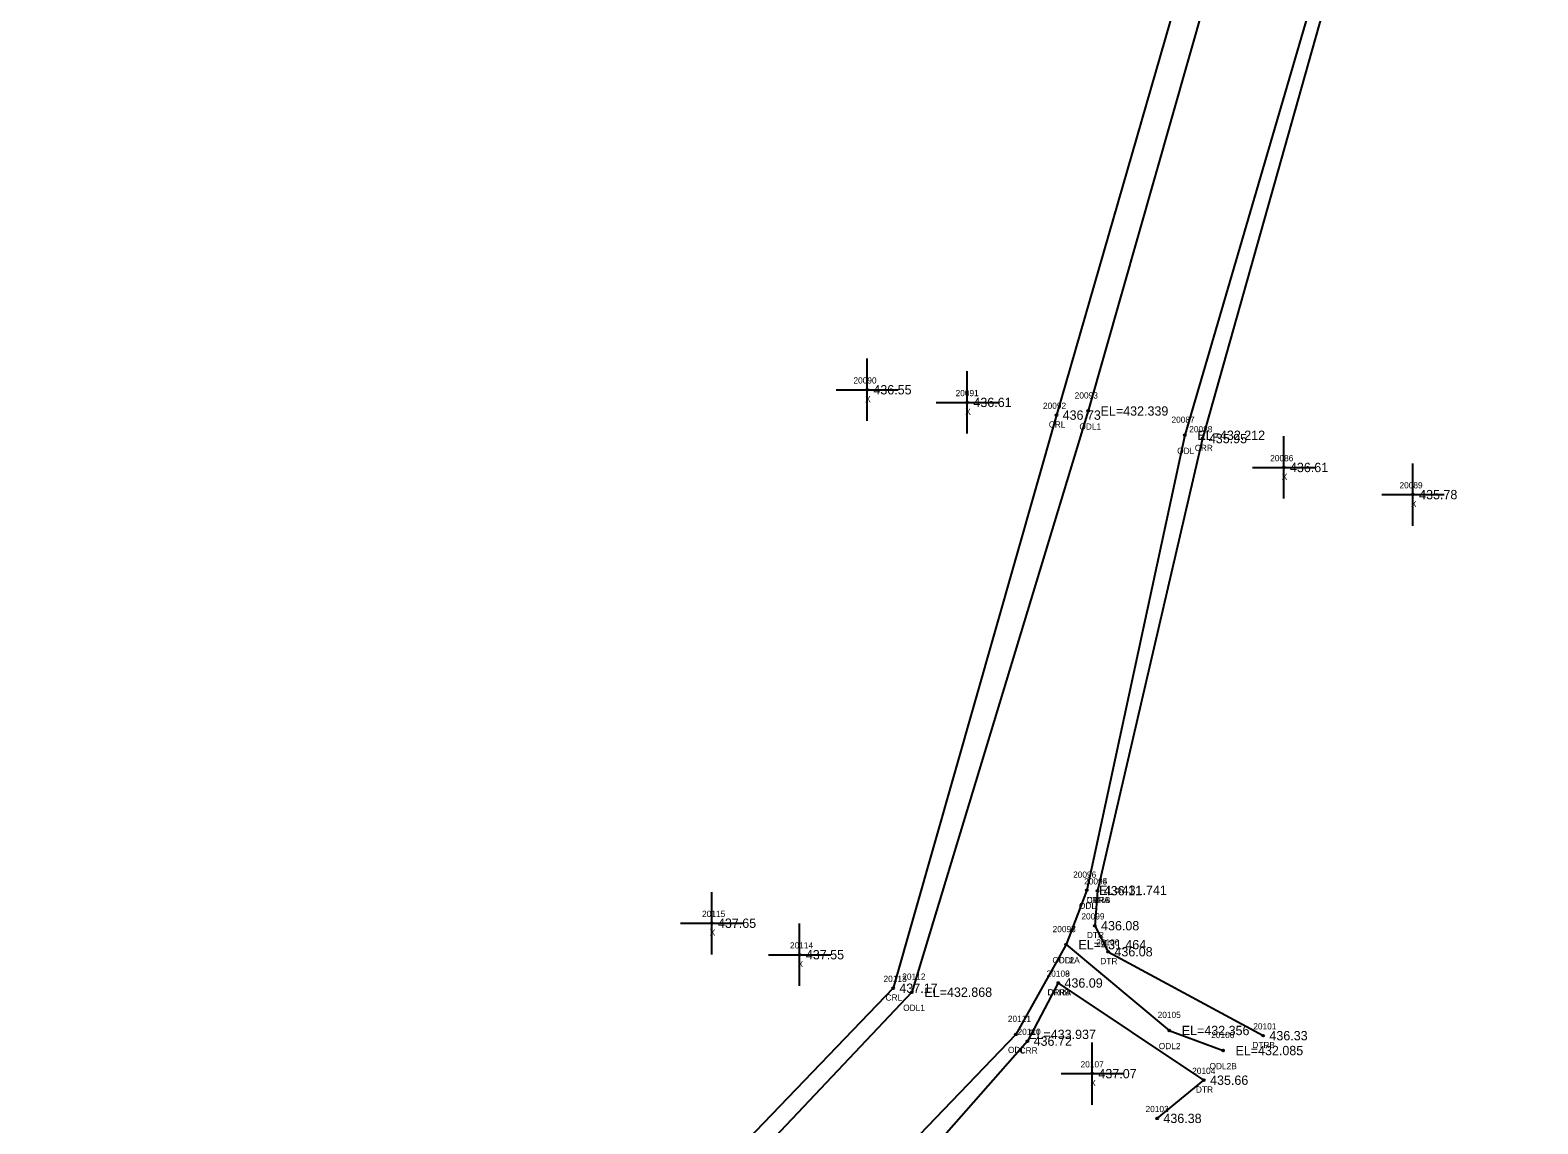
# Model space of a CAD drawing. Extents: x 1810114 to 1811498, y 790790 to 791824.
# Drawn here: x 1810544.9 to 1810787, y 790960.3 to 791135.9 of the extents above; entities that cross this region are included whole.
import ezdxf

# ---------------------------------------------------------------- set-up
doc = ezdxf.new("R2010")
doc.units = 0
for name, color, linetype in [('RD_EX_H2O', 7, 'Continuous'), ('RD_EX_H2O_txCode', 7, 'Continuous'), ('RD_EX_Misc', 7, 'Continuous'), ('RD_EX_Misc_txCode', 7, 'Continuous'), ('RD_EX_TX_H2O_ELEV', 7, 'Continuous'), ('RD_EX_TX_Misc_ELEV', 7, 'Continuous'), ('RD_SMD_Locator', 7, 'Continuous')]:
    doc.layers.add(name, color=color, linetype=linetype)

msp = doc.modelspace()

# ---------------------------------------------------------------- linework, layer by layer
at = {"layer": 'RD_EX_H2O'}
for points in [[(1810767.47, 791275.24), (1810763.99, 791268.4), (1810740.03, 791179.13), (1810709.69, 791074.11), (1810683.47, 790982.07), (1810621.06, 790917.07), (1810544.86, 790829.8)], [(1810771.9, 791274.91), (1810769.68, 791267.55), (1810744.28, 791178.39), (1810714.79, 791074.77), (1810686.49, 790981.43), (1810623.11, 790914.39), (1810548.58, 790826.46)], [(1810781.26, 791266.77), (1810779.82, 791257.8), (1810759.51, 791170.68), (1810730.33, 791070.87), (1810714.55, 790997.81), (1810711.23, 790989.07), (1810703.16, 790974.66), (1810632.29, 790900.83), (1810555.27, 790820.08)], [(1810787.01, 791266.28), (1810783.34, 791255.23), (1810761.16, 791169.77), (1810733.17, 791070.34), (1810716.3, 790997.73)], [(1810716.3, 790997.73), (1810715.86, 790992.11), (1810718.01, 790987.93), (1810742.9, 790974.45)], [(1810711.23, 790989.07), (1810727.82, 790975.28), (1810736.45, 790972.06)], [(1810709.99, 790982.91), (1810705.03, 790973.57), (1810636.85, 790896.09), (1810561.39, 790814.92)], [(1810725.87, 790961.17), (1810733.37, 790967.3), (1810709.99, 790982.91)]]:
    msp.add_lwpolyline(points, dxfattribs=at)
at = {"layer": 'RD_EX_Misc'}
for p, q in [((1810679.29, 791073.18), (1810679.29, 791083.18)), ((1810695.36, 791071.15), (1810695.36, 791081.15)), ((1810674.29, 791078.18), (1810684.29, 791078.18)), ((1810690.36, 791076.15), (1810700.36, 791076.15)), ((1810746.2, 791060.7), (1810746.2, 791070.7)), ((1810741.2, 791065.7), (1810751.2, 791065.7)), ((1810766.95, 791056.34), (1810766.95, 791066.34)), ((1810761.95, 791061.34), (1810771.95, 791061.34)), ((1810654.33, 790987.51), (1810654.33, 790997.51)), ((1810649.33, 790992.51), (1810659.33, 790992.51)), ((1810668.45, 790982.45), (1810668.45, 790992.45)), ((1810663.45, 790987.45), (1810673.45, 790987.45)), ((1810715.44, 790963.35), (1810715.44, 790973.35)), ((1810710.44, 790968.35), (1810720.44, 790968.35))]:
    msp.add_line(p, q, dxfattribs=at)
at = {"layer": 'RD_SMD_Locator'}
for centre in [(1810679.29, 791078.18), (1810695.36, 791076.15), (1810709.69, 791074.11), (1810714.79, 791074.77), (1810730.33, 791070.87), (1810733.17, 791070.34), (1810746.2, 791065.7), (1810766.95, 791061.34), (1810714.55, 790997.81), (1810716.3, 790997.73), (1810716.3, 790997.73), (1810654.33, 790992.51), (1810715.86, 790992.11), (1810668.45, 790987.45), (1810711.23, 790989.07), (1810711.23, 790989.07), (1810718.01, 790987.93), (1810683.47, 790982.07), (1810709.99, 790982.91), (1810709.99, 790982.91), (1810686.49, 790981.43), (1810703.16, 790974.66), (1810727.82, 790975.28), (1810705.03, 790973.57), (1810742.9, 790974.45), (1810736.45, 790972.06), (1810715.44, 790968.35), (1810733.37, 790967.3), (1810725.87, 790961.17)]:
    msp.add_circle(centre, 0.15, dxfattribs=at)

# ---------------------------------------------------------------- texts
at = {"layer": 'RD_EX_H2O_txCode'}
for s, p in [('20093', (1810712.63, 791076.77)), ('20092', (1810707.53, 791075.11)), ('CRL', (1810708.46, 791072.11)), ('ODL1', (1810713.38, 791071.77)), ('20087', (1810728.17, 791072.87)), ('20088', (1810731.02, 791071.34)), ('CRR', (1810731.92, 791068.34)), ('ODL', (1810729.09, 791067.87)), ('20096', (1810712.37, 790999.81)), ('20094', (1810714.14, 790998.73)), ('20095', (1810714.14, 790998.73)), ('CRRB', (1810714.57, 790995.73)), ('DTRA', (1810714.54, 790995.73)), ('ODL', (1810713.31, 790994.81)), ('20099', (1810713.7, 790993.11)), ('20097', (1810709.08, 790991.07)), ('20098', (1810709.08, 790991.07)), ('DTR', (1810714.59, 790990.11)), ('20100', (1810716.09, 790988.93)), ('ODL2A', (1810709.05, 790986.07)), ('ODL', (1810709.99, 790986.07)), ('DTR', (1810716.74, 790985.93)), ('20112', (1810684.94, 790983.43)), ('20108', (1810708.11, 790983.91)), ('20109', (1810708.11, 790983.91)), ('20113', (1810681.92, 790983.07)), ('CRL', (1810682.25, 790980.07)), ('CRRA', (1810708.25, 790980.91)), ('DTRB', (1810708.25, 790980.91)), ('ODL1', (1810685.08, 790978.43)), ('20111', (1810701.89, 790976.66)), ('20105', (1810725.95, 790977.28)), ('20110', (1810703.44, 790974.57)), ('20106', (1810734.55, 790974.06)), ('20101', (1810741.31, 790975.45)), ('ODL', (1810701.91, 790971.66)), ('CRR', (1810703.78, 790971.57)), ('ODL2', (1810726.13, 790972.28)), ('DTRB', (1810741.16, 790972.45)), ('ODL2B', (1810734.28, 790969.06)), ('20104', (1810731.49, 790968.3)), ('DTR', (1810732.1, 790965.3)), ('20103', (1810724, 790962.17))]:
    msp.add_text(s, height=1, dxfattribs=at).set_placement(p)
at = {"layer": 'RD_EX_Misc_txCode'}
for s, p in [('20090', (1810677.09, 791079.18)), ('X', (1810678.98, 791076.18)), ('20091', (1810693.49, 791077.15)), ('X', (1810695.05, 791074.15)), ('20086', (1810744.02, 791066.7)), ('X', (1810745.88, 791063.7)), ('20089', (1810764.79, 791062.34)), ('X', (1810766.63, 791059.34)), ('20115', (1810652.78, 790993.51)), ('X', (1810654.01, 790990.51)), ('20114', (1810666.9, 790988.45)), ('X', (1810668.13, 790985.45)), ('20107', (1810713.57, 790969.35)), ('X', (1810715.13, 790966.35))]:
    msp.add_text(s, height=1, dxfattribs=at).set_placement(p)
at = {"layer": 'RD_EX_TX_H2O_ELEV'}
for s, p in [('436.73', (1810710.69, 791073.36)), ('EL=432.339', (1810716.79, 791074.02)), ('EL=432.212', (1810732.33, 791070.12)), ('435.95', (1810734.17, 791069.59)), ('EL=431.741', (1810716.55, 790997.06)), ('436.11', (1810717.3, 790996.98)), ('436.11', (1810717.3, 790996.98)), ('436.08', (1810716.86, 790991.36)), ('EL=431.464', (1810713.23, 790988.32)), ('EL=431.464', (1810713.23, 790988.32)), ('436.08', (1810719.01, 790987.18)), ('437.17', (1810684.47, 790981.32)), ('EL=432.868', (1810688.49, 790980.68)), ('436.09', (1810710.99, 790982.16)), ('436.09', (1810710.99, 790982.16)), ('EL=433.937', (1810705.16, 790973.91)), ('EL=432.356', (1810729.82, 790974.53)), ('436.33', (1810743.9, 790973.7)), ('436.72', (1810706.03, 790972.82)), ('EL=432.085', (1810738.45, 790971.31)), ('435.66', (1810734.37, 790966.55)), ('436.38', (1810726.87, 790960.42))]:
    msp.add_text(s, height=1.5, dxfattribs=at).set_placement(p)
at = {"layer": 'RD_EX_TX_Misc_ELEV'}
for s, p in [('436.55', (1810680.29, 791077.43)), ('436.61', (1810696.36, 791075.4)), ('436.61', (1810747.2, 791064.95)), ('435.78', (1810767.95, 791060.59)), ('437.65', (1810655.33, 790991.76)), ('437.55', (1810669.45, 790986.7)), ('437.07', (1810716.44, 790967.6))]:
    msp.add_text(s, height=1.5, dxfattribs=at).set_placement(p)

doc.saveas('drawing.dxf')
